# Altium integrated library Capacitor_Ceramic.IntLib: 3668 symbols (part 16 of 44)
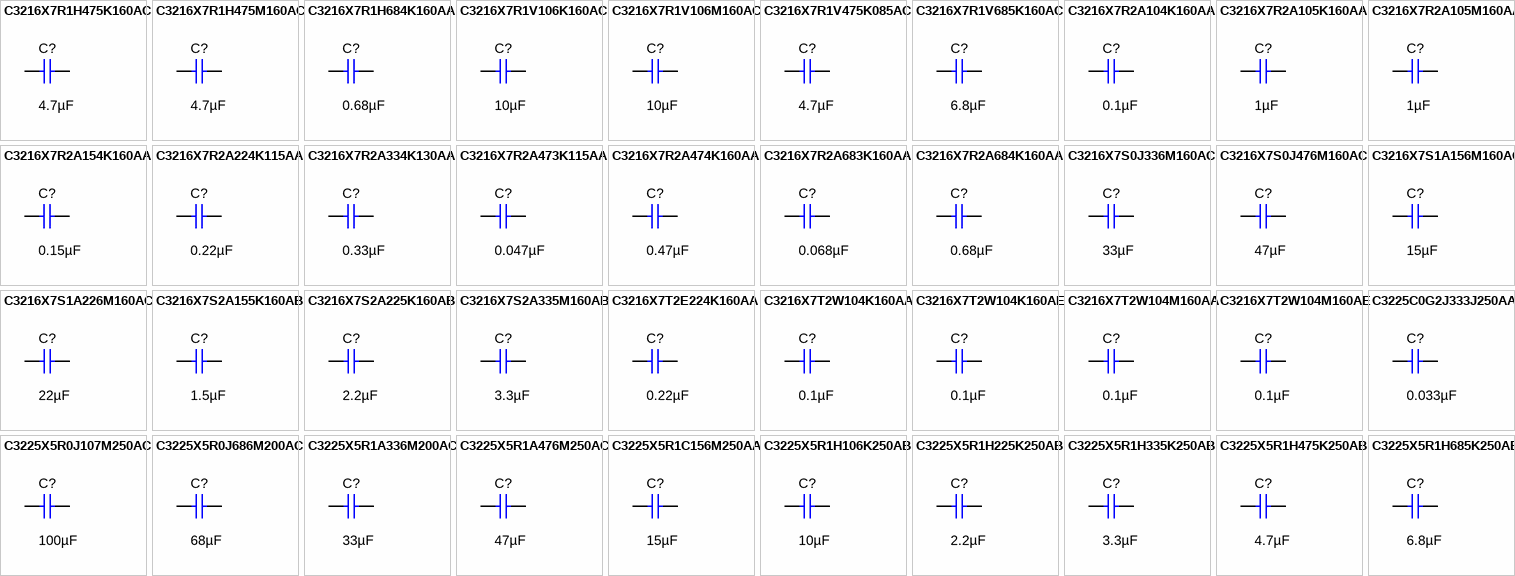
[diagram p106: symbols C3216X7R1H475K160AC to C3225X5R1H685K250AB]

## C3216X7R1H684K160AA
designator C?  ValueDisplayed: 0.68µF  (hidden comment: C3216X7R1H684K160AA)
CAP, CERM, 0.68 µF, 50 V,+/- 10%, X7R, 1206; Manufacturer: TDK; Polarized: N; CompType: Capacitor; Value: 0.68uF; U/M: EA; Cap_F: 0.00000068; Tolerance_%: 10; ESR_ohm: 0.009045; Value1: 0.009045 ohm; VDC_V: 50; Value2: 50V; IRMS_A: 2.41792; TaMin_C: -55; TaMax_C: 125; Cap_Case: 1206; SizeArea_mm2: 5.12; SizeAreaWB_mm2: 10.92; SizeX_mm: 3.2; SizeY_mm: 1.6; SizeZ_mm: 1.8; AEC Category: Q200; Green_Lifecycle: NRND; Green_REACh: Passed
signal-integrity model Cap
simulation model Cap
footprint 1206_180
footprint 1206_180M
footprint 1206_180L
pins: 1, 2

## C3216X7R1V106K160AC
designator C?  ValueDisplayed: 10µF  (hidden comment: C3216X7R1V106K160AC)
CAP, CERM, 10 µF, 35 V,+/- 10%, X7R, 1206; Manufacturer: TDK; Polarized: N; CompType: Capacitor; Value: 10uF; U/M: EA; Cap_F: 0.00001; Tolerance_%: 10; ESR_ohm: 0.002229; Value1: 0.002229 ohm; VDC_V: 35; Value2: 35V; IRMS_A: 4.85932; TaMin_C: -55; TaMax_C: 125; Cap_Case: 1206; SizeArea_mm2: 5.12; SizeAreaWB_mm2: 10.92; SizeX_mm: 3.2; SizeY_mm: 1.6; SizeZ_mm: 1.8; AEC Category: Q200
signal-integrity model Cap
simulation model Cap
footprint 1206_180
footprint 1206_180M
footprint 1206_180L
pins: 1, 2

## C3216X7R1V106M160AC
designator C?  ValueDisplayed: 10µF  (hidden comment: C3216X7R1V106M160AC)
CAP, CERM, 10 µF, 35 V,+/- 20%, X7R, 1206; Manufacturer: TDK; Polarized: N; CompType: Capacitor; Value: 10uF; U/M: EA; Cap_F: 0.00001; Tolerance_%: 20; VDC_V: 35; Value2: 35V; TaMin_C: -55; TaMax_C: 125; Cap_Case: 1206; SizeArea_mm2: 5.12; SizeAreaWB_mm2: 10.92; SizeX_mm: 3.2; SizeY_mm: 1.6; SizeZ_mm: 1.9; AEC Category: Q200; Green_Lifecycle: Active; Green_REACh: Passed
signal-integrity model Cap
simulation model Cap
footprint 1206_190
footprint 1206_190M
footprint 1206_190L
pins: 1, 2

## C3216X7R1V475K085AC
designator C?  ValueDisplayed: 4.7µF  (hidden comment: C3216X7R1V475K085AC)
CAP, CERM, 4.7 µF, 35 V,+/- 10%, X7R, 1206; Manufacturer: TDK; Polarized: N; CompType: Capacitor; Value: 4.7uF; U/M: EA; Cap_F: 0.0000047; Tolerance_%: 10; ESR_ohm: 0.003785; Value1: 0.003785 ohm; VDC_V: 35; Value2: 35V; IRMS_A: 3.73011; TaMin_C: -55; TaMax_C: 125; Cap_Case: 1206; SizeArea_mm2: 5.12; SizeAreaWB_mm2: 10.92; SizeX_mm: 3.2; SizeY_mm: 1.6; SizeZ_mm: 1.35; AEC Category: Q200
signal-integrity model Cap
simulation model Cap
footprint 1206
footprint 1206M
footprint 1206L
pins: 1, 2

## C3216X7R1V685K160AC
designator C?  ValueDisplayed: 6.8µF  (hidden comment: C3216X7R1V685K160AC)
CAP, CERM, 6.8 µF, 35 V,+/- 10%, X7R, 1206; Manufacturer: TDK; Polarized: N; CompType: Capacitor; Value: 6.8uF; U/M: EA; Cap_F: 0.0000068; Tolerance_%: 10; ESR_ohm: 0.003202; Value1: 0.003202 ohm; VDC_V: 35; Value2: 35V; IRMS_A: 4.05527; TaMin_C: -55; TaMax_C: 125; Cap_Case: 1206; SizeArea_mm2: 5.12; SizeAreaWB_mm2: 10.92; SizeX_mm: 3.2; SizeY_mm: 1.6; SizeZ_mm: 1.8; AEC Category: Q200
signal-integrity model Cap
simulation model Cap
footprint 1206_180
footprint 1206_180M
footprint 1206_180L
pins: 1, 2

## C3216X7R2A104K160AA
designator C?  ValueDisplayed: 0.1µF  (hidden comment: C3216X7R2A104K160AA)
CAP, CERM, 0.1 µF, 100 V,+/- 10%, X7R, 1206; Manufacturer: TDK; Polarized: N; CompType: Capacitor; Value: 0.1uF; U/M: EA; Cap_F: 0.0000001; Tolerance_%: 10; ESR_ohm: 0.030343; Value1: 0.030343 ohm; VDC_V: 100; Value2: 100V; IRMS_A: 1.33802; TaMin_C: -55; TaMax_C: 125; Cap_Case: 1206; SizeArea_mm2: 5.12; SizeAreaWB_mm2: 10.92; SizeX_mm: 3.2; SizeY_mm: 1.6; SizeZ_mm: 1.8; AEC Category: Q200; Green_Lifecycle: Active; Green_REACh: Passed
signal-integrity model Cap
simulation model Cap
footprint 1206_180
footprint 1206_180M
footprint 1206_180L
pins: 1, 2

## C3216X7R2A105K160AA
designator C?  ValueDisplayed: 1µF  (hidden comment: C3216X7R2A105K160AA)
CAP, CERM, 1 µF, 100 V,+/- 10%, X7R, 1206; Manufacturer: TDK; Polarized: N; CompType: Capacitor; Value: 1uF; U/M: EA; Cap_F: 0.000001; Tolerance_%: 10; ESR_ohm: 0.004575; Value1: 0.004575 ohm; VDC_V: 100; Value2: 100V; IRMS_A: 3.39639; TaMin_C: -55; TaMax_C: 125; Cap_Case: 1206; SizeArea_mm2: 5.12; SizeAreaWB_mm2: 10.92; SizeX_mm: 3.2; SizeY_mm: 1.6; SizeZ_mm: 1.8; AEC Category: Q200
signal-integrity model Cap
simulation model Cap
footprint 1206_180
footprint 1206_180M
footprint 1206_180L
pins: 1, 2

## C3216X7R2A105M160AA
designator C?  ValueDisplayed: 1µF  (hidden comment: C3216X7R2A105M160AA)
CAP, CERM, 1 µF, 100 V,+/- 20%, X7R, 1206; Manufacturer: TDK; Polarized: N; CompType: Capacitor; Value: 1uF; U/M: EA; Cap_F: 0.000001; Tolerance_%: 20; VDC_V: 100; Value2: 100V; TaMin_C: -55; TaMax_C: 125; Cap_Case: 1206; SizeArea_mm2: 5.12; SizeAreaWB_mm2: 10.92; SizeX_mm: 3.2; SizeY_mm: 1.6; SizeZ_mm: 1.35; AEC Category: Q200; Green_Lifecycle: Active; Green_REACh: Passed
signal-integrity model Cap
simulation model Cap
footprint 1206
footprint 1206M
footprint 1206L
pins: 1, 2

## C3216X7R2A154K160AA
designator C?  ValueDisplayed: 0.15µF  (hidden comment: C3216X7R2A154K160AA)
CAP, CERM, 0.15 µF, 100 V,+/- 10%, X7R, 1206; Manufacturer: TDK; Polarized: N; CompType: Capacitor; Value: 0.15uF; U/M: EA; Cap_F: 0.00000015; Tolerance_%: 10; ESR_ohm: 0.021684; Value1: 0.021684 ohm; VDC_V: 100; Value2: 100V; IRMS_A: 1.57495; TaMin_C: -55; TaMax_C: 125; Cap_Case: 1206; SizeArea_mm2: 5.12; SizeAreaWB_mm2: 10.92; SizeX_mm: 3.2; SizeY_mm: 1.6; SizeZ_mm: 1.8; AEC Category: Q200
signal-integrity model Cap
simulation model Cap
footprint 1206_180
footprint 1206_180M
footprint 1206_180L
pins: 1, 2

## C3216X7R2A224K115AA
designator C?  ValueDisplayed: 0.22µF  (hidden comment: C3216X7R2A224K115AA)
CAP, CERM, 0.22 µF, 100 V,+/- 10%, X7R, 1206; Manufacturer: TDK; Polarized: N; CompType: Capacitor; Value: 0.22uF; U/M: EA; Cap_F: 0.00000022; Tolerance_%: 10; ESR_ohm: 0.01493; Value1: 0.01493 ohm; VDC_V: 100; Value2: 100V; IRMS_A: 1.89056; TaMin_C: -55; TaMax_C: 125; Cap_Case: 1206; SizeArea_mm2: 5.12; SizeAreaWB_mm2: 10.92; SizeX_mm: 3.2; SizeY_mm: 1.6; SizeZ_mm: 1.35; AEC Category: Q200
signal-integrity model Cap
simulation model Cap
footprint 1206
footprint 1206M
footprint 1206L
pins: 1, 2

## C3216X7R2A334K130AA
designator C?  ValueDisplayed: 0.33µF  (hidden comment: C3216X7R2A334K130AA)
CAP, CERM, 0.33 µF, 100 V,+/- 10%, X7R, 1206; Manufacturer: TDK; Polarized: N; CompType: Capacitor; Value: 0.33uF; U/M: EA; Cap_F: 0.00000033; Tolerance_%: 10; ESR_ohm: 0.011504; Value1: 0.011504 ohm; VDC_V: 100; Value2: 100V; IRMS_A: 2.14919; TaMin_C: -55; TaMax_C: 125; Cap_Case: 1206; SizeArea_mm2: 5.12; SizeAreaWB_mm2: 10.92; SizeX_mm: 3.2; SizeY_mm: 1.6; SizeZ_mm: 1.5; AEC Category: Q200
signal-integrity model Cap
simulation model Cap
footprint 1206_150
footprint 1206_150M
footprint 1206_150L
pins: 1, 2

## C3216X7R2A473K115AA
designator C?  ValueDisplayed: 0.047µF  (hidden comment: C3216X7R2A473K115AA)
CAP, CERM, 0.047 µF, 100 V,+/- 10%, X7R, 1206; Manufacturer: TDK; Polarized: N; CompType: Capacitor; Value: 0.047uF; U/M: EA; Cap_F: 0.000000047; Tolerance_%: 10; ESR_ohm: 0.065629; Value1: 0.065629 ohm; VDC_V: 100; Value2: 100V; IRMS_A: 0.927421; TaMin_C: -55; TaMax_C: 125; Cap_Case: 1206; SizeArea_mm2: 5.12; SizeAreaWB_mm2: 10.92; SizeX_mm: 3.2; SizeY_mm: 1.6; SizeZ_mm: 1.35; AEC Category: Q200
signal-integrity model Cap
simulation model Cap
footprint 1206
footprint 1206M
footprint 1206L
pins: 1, 2

## C3216X7R2A474K160AA
designator C?  ValueDisplayed: 0.47µF  (hidden comment: C3216X7R2A474K160AA)
CAP, CERM, 0.47 µF, 100 V,+/- 10%, X7R, 1206; Manufacturer: TDK; Polarized: N; CompType: Capacitor; Value: 0.47uF; U/M: EA; Cap_F: 0.00000047; Tolerance_%: 10; ESR_ohm: 0.007558; Value1: 0.007558 ohm; VDC_V: 100; Value2: 100V; IRMS_A: 2.64716; TaMin_C: -55; TaMax_C: 125; Cap_Case: 1206; SizeArea_mm2: 5.12; SizeAreaWB_mm2: 10.92; SizeX_mm: 3.2; SizeY_mm: 1.6; SizeZ_mm: 1.8; AEC Category: Q200; Green_Lifecycle: Active; Green_REACh: Passed
signal-integrity model Cap
simulation model Cap
footprint 1206_180
footprint 1206_180M
footprint 1206_180L
pins: 1, 2

## C3216X7R2A683K160AA
designator C?  ValueDisplayed: 0.068µF  (hidden comment: C3216X7R2A683K160AA)
CAP, CERM, 0.068 µF, 100 V,+/- 10%, X7R, 1206; Manufacturer: TDK; Polarized: N; CompType: Capacitor; Value: 0.068uF; U/M: EA; Cap_F: 0.000000068; Tolerance_%: 10; ESR_ohm: 0.046525; Value1: 0.046525 ohm; VDC_V: 100; Value2: 100V; IRMS_A: 1.08982; TaMin_C: -55; TaMax_C: 125; Cap_Case: 1206; SizeArea_mm2: 5.12; SizeAreaWB_mm2: 10.92; SizeX_mm: 3.2; SizeY_mm: 1.6; SizeZ_mm: 1.8; AEC Category: Q200
signal-integrity model Cap
simulation model Cap
footprint 1206_180
footprint 1206_180M
footprint 1206_180L
pins: 1, 2

## C3216X7R2A684K160AA
designator C?  ValueDisplayed: 0.68µF  (hidden comment: C3216X7R2A684K160AA)
CAP, CERM, 0.68 µF, 100 V,+/- 10%, X7R, 1206; Manufacturer: TDK; Polarized: N; CompType: Capacitor; Value: 0.68uF; U/M: EA; Cap_F: 0.00000068; Tolerance_%: 10; ESR_ohm: 0.007371; Value1: 0.007371 ohm; VDC_V: 100; Value2: 100V; IRMS_A: 2.67843; TaMin_C: -55; TaMax_C: 125; Cap_Case: 1206; SizeArea_mm2: 5.12; SizeAreaWB_mm2: 10.92; SizeX_mm: 3.2; SizeY_mm: 1.6; SizeZ_mm: 1.8; AEC Category: Q200
signal-integrity model Cap
simulation model Cap
footprint 1206_180
footprint 1206_180M
footprint 1206_180L
pins: 1, 2

## C3216X7S0J336M160AC
designator C?  ValueDisplayed: 33µF  (hidden comment: C3216X7S0J336M160AC)
CAP, CERM, 33 µF, 6.3 V,+/- 20%, X7S, 1206; Manufacturer: TDK; Polarized: N; CompType: Capacitor; Value: 33uF; U/M: EA; Cap_F: 0.000033; Tolerance_%: 20; ESR_ohm: 0.002648; Value1: 0.002648 ohm; VDC_V: 6.3; Value2: 6.3V; IRMS_A: 4.45864; TaMin_C: -55; TaMax_C: 125; Cap_Case: 1206; SizeArea_mm2: 5.12; SizeAreaWB_mm2: 10.92; SizeX_mm: 3.2; SizeY_mm: 1.6; SizeZ_mm: 1.8; AEC Category: Q200
signal-integrity model Cap
simulation model Cap
footprint 1206_180
footprint 1206_180M
footprint 1206_180L
pins: 1, 2

## C3216X7S0J476M160AC
designator C?  ValueDisplayed: 47µF  (hidden comment: C3216X7S0J476M160AC)
CAP, CERM, 47 µF, 6.3 V,+/- 20%, X7S, 1206; Manufacturer: TDK; Polarized: N; CompType: Capacitor; Value: 47uF; U/M: EA; Cap_F: 0.000047; Tolerance_%: 20; ESR_ohm: 0.002082; Value1: 0.002082 ohm; VDC_V: 6.3; Value2: 6.3V; IRMS_A: 5.02786; TaMin_C: -55; TaMax_C: 125; Cap_Case: 1206; SizeArea_mm2: 5.12; SizeAreaWB_mm2: 10.92; SizeX_mm: 3.2; SizeY_mm: 1.6; SizeZ_mm: 1.8; AEC Category: Q200
signal-integrity model Cap
simulation model Cap
footprint 1206_180
footprint 1206_180M
footprint 1206_180L
pins: 1, 2

## C3216X7S1A156M160AC
designator C?  ValueDisplayed: 15µF  (hidden comment: C3216X7S1A156M160AC)
CAP, CERM, 15 µF, 10 V,+/- 20%, X7S, 1206; Manufacturer: TDK; Polarized: N; CompType: Capacitor; Value: 15uF; U/M: EA; Cap_F: 0.000015; Tolerance_%: 20; ESR_ohm: 0.002667; Value1: 0.002667 ohm; VDC_V: 10; Value2: 10V; IRMS_A: 4.44289; TaMin_C: -55; TaMax_C: 125; Cap_Case: 1206; SizeArea_mm2: 5.12; SizeAreaWB_mm2: 10.92; SizeX_mm: 3.2; SizeY_mm: 1.6; SizeZ_mm: 1.8; AEC Category: Q200
signal-integrity model Cap
simulation model Cap
footprint 1206_180
footprint 1206_180M
footprint 1206_180L
pins: 1, 2

## C3216X7S1A226M160AC
designator C?  ValueDisplayed: 22µF  (hidden comment: C3216X7S1A226M160AC)
CAP, CERM, 22 µF, 10 V,+/- 20%, X7S, 1206; Manufacturer: TDK; Polarized: N; CompType: Capacitor; Value: 22uF; U/M: EA; Cap_F: 0.000022; Tolerance_%: 20; ESR_ohm: 0.002398; Value1: 0.002398 ohm; VDC_V: 10; Value2: 10V; IRMS_A: 4.68507; TaMin_C: -55; TaMax_C: 125; Cap_Case: 1206; SizeArea_mm2: 5.12; SizeAreaWB_mm2: 10.92; SizeX_mm: 3.2; SizeY_mm: 1.6; SizeZ_mm: 1.8; AEC Category: Q200
signal-integrity model Cap
simulation model Cap
footprint 1206_180
footprint 1206_180M
footprint 1206_180L
pins: 1, 2

## C3216X7S2A155K160AB
designator C?  ValueDisplayed: 1.5µF  (hidden comment: C3216X7S2A155K160AB)
CAP, CERM, 1.5 µF, 100 V,+/- 10%, X7S, 1206; Manufacturer: TDK; Polarized: N; CompType: Capacitor; Value: 1.5uF; U/M: EA; Cap_F: 0.0000015; Tolerance_%: 10; ESR_ohm: 0.006319; Value1: 0.006319 ohm; VDC_V: 100; Value2: 100V; IRMS_A: 2.88897; TaMin_C: -55; TaMax_C: 125; Cap_Case: 1206; SizeArea_mm2: 5.12; SizeAreaWB_mm2: 10.92; SizeX_mm: 3.2; SizeY_mm: 1.6; SizeZ_mm: 1.8; AEC Category: Q200
signal-integrity model Cap
simulation model Cap
footprint 1206_180
footprint 1206_180M
footprint 1206_180L
pins: 1, 2

## C3216X7S2A225K160AB
designator C?  ValueDisplayed: 2.2µF  (hidden comment: C3216X7S2A225K160AB)
CAP, CERM, 2.2 µF, 100 V,+/- 10%, X7S, 1206; Manufacturer: TDK; Polarized: N; CompType: Capacitor; Value: 2.2uF; U/M: EA; Cap_F: 0.0000022; Tolerance_%: 10; ESR_ohm: 0.005718; Value1: 0.005718 ohm; VDC_V: 100; Value2: 100V; IRMS_A: 3.03632; TaMin_C: -55; TaMax_C: 125; Cap_Case: 1206; SizeArea_mm2: 5.12; SizeAreaWB_mm2: 10.92; SizeX_mm: 3.2; SizeY_mm: 1.6; SizeZ_mm: 1.8; AEC Category: Q200
signal-integrity model Cap
simulation model Cap
footprint 1206_180
footprint 1206_180M
footprint 1206_180L
pins: 1, 2

## C3216X7S2A335M160AB
designator C?  ValueDisplayed: 3.3µF  (hidden comment: C3216X7S2A335M160AB)
CAP, CERM, 3.3 µF, 100 V,+/- 20%, X7S, 1206; Manufacturer: TDK; Polarized: N; CompType: Capacitor; Value: 3.3uF; U/M: EA; Cap_F: 0.0000033; Tolerance_%: 20; ESR_ohm: 0.003048; Value1: 0.003048 ohm; VDC_V: 100; Value2: 100V; IRMS_A: 4.15703; TaMin_C: -55; TaMax_C: 125; Cap_Case: 1206; SizeArea_mm2: 5.12; SizeAreaWB_mm2: 10.92; SizeX_mm: 3.2; SizeY_mm: 1.6; SizeZ_mm: 1.9; AEC Category: Q200
signal-integrity model Cap
simulation model Cap
footprint 1206_190
footprint 1206_190M
footprint 1206_190L
pins: 1, 2

## C3216X7T2E224K160AA
designator C?  ValueDisplayed: 0.22µF  (hidden comment: C3216X7T2E224K160AA)
CAP, CERM, 0.22 µF, 250 V,+/- 10%, X7T, 1206; Manufacturer: TDK; Polarized: N; CompType: Capacitor; Value: 0.22uF; U/M: EA; Cap_F: 0.00000022; Tolerance_%: 10; VDC_V: 250; Value2: 250V; TaMin_C: -55; TaMax_C: 125; Cap_Case: 1206; SizeArea_mm2: 5.12; SizeAreaWB_mm2: 10.92; SizeX_mm: 3.2; SizeY_mm: 1.6; SizeZ_mm: 1.9; AEC Category: Q200; Green_Lifecycle: Active; Green_REACh: Passed
signal-integrity model Cap
simulation model Cap
footprint 1206_190
footprint 1206_190M
footprint 1206_190L
pins: 1, 2

## C3216X7T2W104K160AA
designator C?  ValueDisplayed: 0.1µF  (hidden comment: C3216X7T2W104K160AA)
CAP, CERM, 0.1 µF, 450 V,+/- 10%, X7T, 1206; Manufacturer: TDK; Polarized: N; CompType: Capacitor; Value: 0.1uF; U/M: EA; Cap_F: 0.0000001; Tolerance_%: 10; VDC_V: 450; Value2: 450V; TaMin_C: -55; TaMax_C: 125; Cap_Case: 1206; SizeArea_mm2: 5.12; SizeAreaWB_mm2: 10.92; SizeX_mm: 3.2; SizeY_mm: 1.6; SizeZ_mm: 1.9; AEC Category: Q200; Green_Lifecycle: Not Set; Green_REACh: Incomplete
signal-integrity model Cap
simulation model Cap
footprint 1206_190
footprint 1206_190M
footprint 1206_190L
pins: 1, 2

## C3216X7T2W104K160AE
designator C?  ValueDisplayed: 0.1µF  (hidden comment: C3216X7T2W104K160AE)
CAP, CERM, 0.1 µF, 450 V,+/- 10%, X7T, 1206; Manufacturer: TDK; Polarized: N; CompType: Capacitor; Value: 0.1uF; U/M: EA; Cap_F: 0.0000001; Tolerance_%: 10; VDC_V: 450; Value2: 450V; TaMin_C: -55; TaMax_C: 125; Cap_Case: 1206; SizeArea_mm2: 5.12; SizeAreaWB_mm2: 10.92; SizeX_mm: 3.2; SizeY_mm: 1.6; SizeZ_mm: 1.8; AEC Category: Q200; Green_Lifecycle: Not Set; Green_REACh: Incomplete
signal-integrity model Cap
simulation model Cap
footprint 1206_180
footprint 1206_180M
footprint 1206_180L
pins: 1, 2

## C3216X7T2W104M160AA
designator C?  ValueDisplayed: 0.1µF  (hidden comment: C3216X7T2W104M160AA)
CAP, CERM, 0.1 µF, 450 V,+/- 20%, X7T, 1206; Manufacturer: TDK; Polarized: N; CompType: Capacitor; Value: 0.1uF; U/M: EA; Cap_F: 0.0000001; Tolerance_%: 20; VDC_V: 450; Value2: 450V; TaMin_C: -55; TaMax_C: 125; Cap_Case: 1206; SizeArea_mm2: 5.12; SizeAreaWB_mm2: 10.92; SizeX_mm: 3.2; SizeY_mm: 1.6; SizeZ_mm: 1.8; AEC Category: Q200; Green_Lifecycle: Not Set; Green_REACh: Incomplete
signal-integrity model Cap
simulation model Cap
footprint 1206_180
footprint 1206_180M
footprint 1206_180L
pins: 1, 2

## C3216X7T2W104M160AE
designator C?  ValueDisplayed: 0.1µF  (hidden comment: C3216X7T2W104M160AE)
CAP, CERM, 0.1 µF, 450 V,+/- 20%, X7T, 1206; Manufacturer: TDK; Polarized: N; CompType: Capacitor; Value: 0.1uF; U/M: EA; Cap_F: 0.0000001; Tolerance_%: 20; VDC_V: 450; Value2: 450V; TaMin_C: -55; TaMax_C: 125; Cap_Case: 1206; SizeArea_mm2: 5.12; SizeAreaWB_mm2: 10.92; SizeX_mm: 3.2; SizeY_mm: 1.6; SizeZ_mm: 1.8; AEC Category: Q200; Green_Lifecycle: Not Set; Green_REACh: Incomplete
signal-integrity model Cap
simulation model Cap
footprint 1206_180
footprint 1206_180M
footprint 1206_180L
pins: 1, 2

## C3225C0G2J333J250AA
designator C?  ValueDisplayed: 0.033µF  (hidden comment: C3225C0G2J333J250AA)
CAP, CERM, 0.033 µF, 630 V,+/- 5%, C0G/NP0, 1210; Manufacturer: TDK; Polarized: N; CompType: Capacitor; Value: 0.033uF; U/M: EA; Cap_F: 0.000000033; Tolerance_%: 5; VDC_V: 630; Value2: 630V; TaMin_C: -55; TaMax_C: 125; Cap_Case: 1210; SizeArea_mm2: 8; SizeAreaWB_mm2: 14.7; SizeX_mm: 3.2; SizeY_mm: 2.5; SizeZ_mm: 2.8; AEC Category: Q200
signal-integrity model Cap
simulation model Cap
footprint 1210_280
pins: 1, 2

## C3225X5R0J107M250AC
designator C?  ValueDisplayed: 100µF  (hidden comment: C3225X5R0J107M250AC)
CAP, CERM, 100 µF, 6.3 V,+/- 20%, X5R, 1210; Manufacturer: TDK; Polarized: N; CompType: Capacitor; Value: 100uF; U/M: EA; Cap_F: 0.0001; Tolerance_%: 20; ESR_ohm: 0.005496; Value1: 0.005496 ohm; VDC_V: 6.3; Value2: 6.3V; IRMS_A: 3.13651; TaMin_C: -55; TaMax_C: 85; Cap_Case: 1210; SizeArea_mm2: 8; SizeAreaWB_mm2: 14.7; SizeX_mm: 3.2; SizeY_mm: 2.5; SizeZ_mm: 2.8; AEC Category: Q200; Green_Lifecycle: Active; Green_REACh: Passed
signal-integrity model Cap
simulation model Cap
footprint 1210_280
pins: 1, 2

## C3225X5R0J686M200AC
designator C?  ValueDisplayed: 68µF  (hidden comment: C3225X5R0J686M200AC)
CAP, CERM, 68 µF, 6.3 V,+/- 20%, X5R, 1210; Manufacturer: TDK; Polarized: N; CompType: Capacitor; Value: 68uF; U/M: EA; Cap_F: 0.000068; Tolerance_%: 20; ESR_ohm: 0.001888; Value1: 0.001888 ohm; VDC_V: 6.3; Value2: 6.3V; IRMS_A: 5.35045; TaMin_C: -55; TaMax_C: 85; Cap_Case: 1210; SizeArea_mm2: 8; SizeAreaWB_mm2: 14.7; SizeX_mm: 3.2; SizeY_mm: 2.5; SizeZ_mm: 2.2; AEC Category: Q200
signal-integrity model Cap
simulation model Cap
footprint 1210_220
footprint 1210_220M
footprint 1210_220L
pins: 1, 2

## C3225X5R1A336M200AC
designator C?  ValueDisplayed: 33µF  (hidden comment: C3225X5R1A336M200AC)
CAP, CERM, 33 µF, 10 V,+/- 20%, X5R, 1210; Manufacturer: TDK; Polarized: N; CompType: Capacitor; Value: 33uF; U/M: EA; Cap_F: 0.000033; Tolerance_%: 20; ESR_ohm: 0.00252; Value1: 0.00252 ohm; VDC_V: 10; Value2: 10V; IRMS_A: 4.63172; TaMin_C: -55; TaMax_C: 85; Cap_Case: 1210; SizeArea_mm2: 8; SizeAreaWB_mm2: 14.7; SizeX_mm: 3.2; SizeY_mm: 2.5; SizeZ_mm: 2.2; AEC Category: Q200
signal-integrity model Cap
simulation model Cap
footprint 1210_220
footprint 1210_220M
footprint 1210_220L
pins: 1, 2

## C3225X5R1A476M250AC
designator C?  ValueDisplayed: 47µF  (hidden comment: C3225X5R1A476M250AC)
CAP, CERM, 47 µF, 10 V,+/- 20%, X5R, 1210; Manufacturer: TDK; Polarized: N; CompType: Capacitor; Value: 47uF; U/M: EA; Cap_F: 0.000047; Tolerance_%: 20; ESR_ohm: 0.003602; Value1: 0.003602 ohm; VDC_V: 10; Value2: 10V; IRMS_A: 3.87414; TaMin_C: -55; TaMax_C: 85; Cap_Case: 1210; SizeArea_mm2: 8; SizeAreaWB_mm2: 14.7; SizeX_mm: 3.2; SizeY_mm: 2.5; SizeZ_mm: 2.8; AEC Category: Q200; Green_Lifecycle: Active; Green_REACh: Passed
signal-integrity model Cap
simulation model Cap
footprint 1210_280
pins: 1, 2

## C3225X5R1C156M250AA
designator C?  ValueDisplayed: 15µF  (hidden comment: C3225X5R1C156M250AA)
CAP, CERM, 15 µF, 16 V,+/- 20%, X5R, 1210; Manufacturer: TDK; Polarized: N; CompType: Capacitor; Value: 15uF; U/M: EA; Cap_F: 0.000015; Tolerance_%: 20; ESR_ohm: 0.002949; Value1: 0.002949 ohm; VDC_V: 16; Value2: 16V; IRMS_A: 4.28133; TaMin_C: -55; TaMax_C: 85; Cap_Case: 1210; SizeArea_mm2: 8; SizeAreaWB_mm2: 14.7; SizeX_mm: 3.2; SizeY_mm: 2.5; SizeZ_mm: 2.8; AEC Category: Q200
signal-integrity model Cap
simulation model Cap
footprint 1210_280
pins: 1, 2

## C3225X5R1H106K250AB
designator C?  ValueDisplayed: 10µF  (hidden comment: C3225X5R1H106K250AB)
CAP, CERM, 10 µF, 50 V,+/- 10%, X5R, 1210; Manufacturer: TDK; Polarized: N; CompType: Capacitor; Value: 10uF; U/M: EA; Cap_F: 0.00001; Tolerance_%: 10; VDC_V: 50; Value2: 50V; TaMin_C: -55; TaMax_C: 85; Cap_Case: 1210; SizeArea_mm2: 8; SizeAreaWB_mm2: 14.7; SizeX_mm: 3.2; SizeY_mm: 2.5; SizeZ_mm: 2.8; AEC Category: Q200; Green_Lifecycle: Active; Green_REACh: Passed
signal-integrity model Cap
simulation model Cap
footprint 1210_280
pins: 1, 2

## C3225X5R1H225K250AB
designator C?  ValueDisplayed: 2.2µF  (hidden comment: C3225X5R1H225K250AB)
CAP, CERM, 2.2 µF, 50 V,+/- 10%, X5R, 1210; Manufacturer: TDK; Polarized: N; CompType: Capacitor; Value: 2.2uF; U/M: EA; Cap_F: 0.0000022; Tolerance_%: 10; ESR_ohm: 0.00536; Value1: 0.00536 ohm; VDC_V: 50; Value2: 50V; IRMS_A: 3.17778; TaMin_C: -55; TaMax_C: 85; Cap_Case: 1210; SizeArea_mm2: 8; SizeAreaWB_mm2: 14.7; SizeX_mm: 3.2; SizeY_mm: 2.5; SizeZ_mm: 2.8; AEC Category: Q200
signal-integrity model Cap
simulation model Cap
footprint 1210_280
pins: 1, 2

## C3225X5R1H335K250AB
designator C?  ValueDisplayed: 3.3µF  (hidden comment: C3225X5R1H335K250AB)
CAP, CERM, 3.3 µF, 50 V,+/- 10%, X5R, 1210; Manufacturer: TDK; Polarized: N; CompType: Capacitor; Value: 3.3uF; U/M: EA; Cap_F: 0.0000033; Tolerance_%: 10; ESR_ohm: 0.003158; Value1: 0.003158 ohm; VDC_V: 50; Value2: 50V; IRMS_A: 4.13891; TaMin_C: -55; TaMax_C: 85; Cap_Case: 1210; SizeArea_mm2: 8; SizeAreaWB_mm2: 14.7; SizeX_mm: 3.2; SizeY_mm: 2.5; SizeZ_mm: 2.8; AEC Category: Q200
signal-integrity model Cap
simulation model Cap
footprint 1210_280
pins: 1, 2

## C3225X5R1H475K250AB
designator C?  ValueDisplayed: 4.7µF  (hidden comment: C3225X5R1H475K250AB)
CAP, CERM, 4.7 µF, 50 V,+/- 10%, X5R, 1210; Manufacturer: TDK; Polarized: N; CompType: Capacitor; Value: 4.7uF; U/M: EA; Cap_F: 0.0000047; Tolerance_%: 10; ESR_ohm: 0.003166; Value1: 0.003166 ohm; VDC_V: 50; Value2: 50V; IRMS_A: 4.13311; TaMin_C: -55; TaMax_C: 85; Cap_Case: 1210; SizeArea_mm2: 8; SizeAreaWB_mm2: 14.7; SizeX_mm: 3.2; SizeY_mm: 2.5; SizeZ_mm: 2.8; AEC Category: Q200; Green_Lifecycle: NRND; Green_REACh: Passed
signal-integrity model Cap
simulation model Cap
footprint 1210_280
pins: 1, 2

## C3225X5R1H685K250AB
designator C?  ValueDisplayed: 6.8µF  (hidden comment: C3225X5R1H685K250AB)
CAP, CERM, 6.8 µF, 50 V,+/- 10%, X5R, 1210; Manufacturer: TDK; Polarized: N; CompType: Capacitor; Value: 6.8uF; U/M: EA; Cap_F: 0.0000068; Tolerance_%: 10; ESR_ohm: 0.002622; Value1: 0.002622 ohm; VDC_V: 50; Value2: 50V; IRMS_A: 4.5415; TaMin_C: -55; TaMax_C: 85; Cap_Case: 1210; SizeArea_mm2: 8; SizeAreaWB_mm2: 14.7; SizeX_mm: 3.2; SizeY_mm: 2.5; SizeZ_mm: 2.8; AEC Category: Q200
signal-integrity model Cap
simulation model Cap
footprint 1210_280
pins: 1, 2

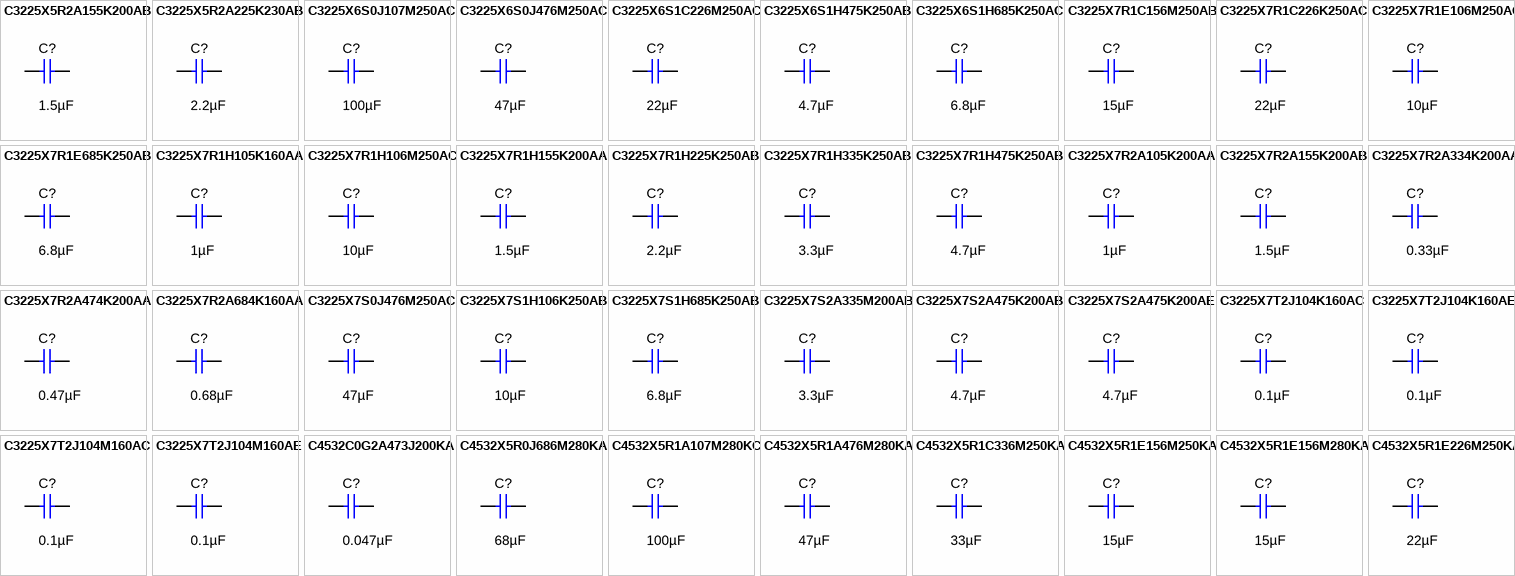
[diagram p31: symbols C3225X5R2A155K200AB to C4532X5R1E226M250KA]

## C3225X5R2A155K200AB
designator C?  ValueDisplayed: 1.5µF  (hidden comment: C3225X5R2A155K200AB)
CAP, CERM, 1.5 µF, 100 V,+/- 10%, X5R, 1210; Manufacturer: TDK; Polarized: N; CompType: Capacitor; Value: 1.5uF; U/M: EA; Cap_F: 0.0000015; Tolerance_%: 10; ESR_ohm: 0.003867; Value1: 0.003867 ohm; VDC_V: 100; Value2: 100V; IRMS_A: 3.74252; TaMin_C: -55; TaMax_C: 85; Cap_Case: 1210; SizeArea_mm2: 8; SizeAreaWB_mm2: 14.7; SizeX_mm: 3.2; SizeY_mm: 2.5; SizeZ_mm: 2.2; AEC Category: Q200
signal-integrity model Cap
simulation model Cap
footprint 1210_220
footprint 1210_220M
footprint 1210_220L
pins: 1, 2

## C3225X5R2A225K230AB
designator C?  ValueDisplayed: 2.2µF  (hidden comment: C3225X5R2A225K230AB)
CAP, CERM, 2.2 µF, 100 V,+/- 10%, X5R, 1210; Manufacturer: TDK; Polarized: N; CompType: Capacitor; Value: 2.2uF; U/M: EA; Cap_F: 0.0000022; Tolerance_%: 10; ESR_ohm: 0.00173; Value1: 0.00173 ohm; VDC_V: 100; Value2: 100V; IRMS_A: 5.59317; TaMin_C: -55; TaMax_C: 85; Cap_Case: 1210; SizeArea_mm2: 8; SizeAreaWB_mm2: 14.7; SizeX_mm: 3.2; SizeY_mm: 2.5; AEC Category: Q200; Green_Lifecycle: NRND; Green_REACh: Passed
signal-integrity model Cap
simulation model Cap
footprint 1210_250
footprint 1210_250M
footprint 1210_250L
pins: 1, 2

## C3225X6S0J107M250AC
designator C?  ValueDisplayed: 100µF  (hidden comment: C3225X6S0J107M250AC)
CAP, CERM, 100 µF, 6.3 V,+/- 20%, X6S, 1210; Manufacturer: TDK; Polarized: N; CompType: Capacitor; Value: 100uF; U/M: EA; Cap_F: 0.0001; Tolerance_%: 20; ESR_ohm: 0.005496; Value1: 0.005496 ohm; VDC_V: 6.3; Value2: 6.3V; IRMS_A: 3.13651; TaMin_C: -55; TaMax_C: 105; Cap_Case: 1210; SizeArea_mm2: 8; SizeAreaWB_mm2: 14.7; SizeX_mm: 3.2; SizeY_mm: 2.5; SizeZ_mm: 2.8; AEC Category: Q200
signal-integrity model Cap
simulation model Cap
footprint 1210_280
pins: 1, 2

## C3225X6S0J476M250AC
designator C?  ValueDisplayed: 47µF  (hidden comment: C3225X6S0J476M250AC)
CAP, CERM, 47 µF, 6.3 V,+/- 20%, X6S, 1210; Manufacturer: TDK; Polarized: N; CompType: Capacitor; Value: 47uF; U/M: EA; Cap_F: 0.000047; Tolerance_%: 20; ESR_ohm: 0.003602; Value1: 0.003602 ohm; VDC_V: 6.3; Value2: 6.3V; IRMS_A: 3.87414; TaMin_C: -55; TaMax_C: 105; Cap_Case: 1210; SizeArea_mm2: 8; SizeAreaWB_mm2: 14.7; SizeX_mm: 3.2; SizeY_mm: 2.5; SizeZ_mm: 2.8; AEC Category: Q200
signal-integrity model Cap
simulation model Cap
footprint 1210_280
pins: 1, 2

## C3225X6S1C226M250AC
designator C?  ValueDisplayed: 22µF  (hidden comment: C3225X6S1C226M250AC)
CAP, CERM, 22 µF, 16 V,+/- 20%, X6S, 1210; Manufacturer: TDK; Polarized: N; CompType: Capacitor; Value: 22uF; U/M: EA; Cap_F: 0.000022; Tolerance_%: 20; ESR_ohm: 0.002582; Value1: 0.002582 ohm; VDC_V: 16; Value2: 16V; IRMS_A: 4.57562; TaMin_C: -55; TaMax_C: 105; Cap_Case: 1210; SizeArea_mm2: 8; SizeAreaWB_mm2: 14.7; SizeX_mm: 3.2; SizeY_mm: 2.5; SizeZ_mm: 2.8; AEC Category: Q200
signal-integrity model Cap
simulation model Cap
footprint 1210_280
pins: 1, 2

## C3225X6S1H475K250AB
designator C?  ValueDisplayed: 4.7µF  (hidden comment: C3225X6S1H475K250AB)
CAP, CERM, 4.7 µF, 50 V,+/- 10%, X6S, 1210; Manufacturer: TDK; Polarized: N; CompType: Capacitor; Value: 4.7uF; U/M: EA; Cap_F: 0.0000047; Tolerance_%: 10; ESR_ohm: 0.003166; Value1: 0.003166 ohm; VDC_V: 50; Value2: 50V; IRMS_A: 4.13311; TaMin_C: -55; TaMax_C: 105; Cap_Case: 1210; SizeArea_mm2: 8; SizeAreaWB_mm2: 14.7; SizeX_mm: 3.2; SizeY_mm: 2.5; SizeZ_mm: 2.8; AEC Category: Q200
signal-integrity model Cap
simulation model Cap
footprint 1210_280
pins: 1, 2

## C3225X6S1H685K250AC
designator C?  ValueDisplayed: 6.8µF  (hidden comment: C3225X6S1H685K250AC)
CAP, CERM, 6.8 µF, 50 V,+/- 10%, X6S, 1210; Manufacturer: TDK; Polarized: N; CompType: Capacitor; Value: 6.8uF; U/M: EA; Cap_F: 0.0000068; Tolerance_%: 10; ESR_ohm: 0.002622; Value1: 0.002622 ohm; VDC_V: 50; Value2: 50V; IRMS_A: 4.5415; TaMin_C: -55; TaMax_C: 105; Cap_Case: 1210; SizeArea_mm2: 8; SizeAreaWB_mm2: 14.7; SizeX_mm: 3.2; SizeY_mm: 2.5; SizeZ_mm: 2.8; AEC Category: Q200
signal-integrity model Cap
simulation model Cap
footprint 1210_280
pins: 1, 2

## C3225X7R1C156M250AB
designator C?  ValueDisplayed: 15µF  (hidden comment: C3225X7R1C156M250AB)
CAP, CERM, 15 µF, 16 V,+/- 20%, X7R, 1210; Manufacturer: TDK; Polarized: N; CompType: Capacitor; Value: 15uF; U/M: EA; Cap_F: 0.000015; Tolerance_%: 20; ESR_ohm: 0.002949; Value1: 0.002949 ohm; VDC_V: 16; Value2: 16V; IRMS_A: 4.28133; TaMin_C: -55; TaMax_C: 125; Cap_Case: 1210; SizeArea_mm2: 8; SizeAreaWB_mm2: 14.7; SizeX_mm: 3.2; SizeY_mm: 2.5; SizeZ_mm: 2.8; AEC Category: Q200
signal-integrity model Cap
simulation model Cap
footprint 1210_280
pins: 1, 2

## C3225X7R1C226K250AC
designator C?  ValueDisplayed: 22µF  (hidden comment: C3225X7R1C226K250AC)
CAP, CERM, 22 µF, 16 V,+/- 10%, X7R, 1210; Manufacturer: TDK; Polarized: N; CompType: Capacitor; Value: 22uF; U/M: EA; Cap_F: 0.000022; Tolerance_%: 10; ESR_ohm: 0.002582; Value1: 0.002582 ohm; VDC_V: 16; Value2: 16V; IRMS_A: 4.57562; TaMin_C: -55; TaMax_C: 125; Cap_Case: 1210; SizeArea_mm2: 8; SizeAreaWB_mm2: 14.7; SizeX_mm: 3.2; SizeY_mm: 2.5; SizeZ_mm: 2.8; AEC Category: Q200; Green_Lifecycle: Active; Green_REACh: Passed
signal-integrity model Cap
simulation model Cap
footprint 1210_280
pins: 1, 2

## C3225X7R1E106M250AC
designator C?  ValueDisplayed: 10µF  (hidden comment: C3225X7R1E106M250AC)
CAP, CERM, 10 µF, 25 V,+/- 20%, X7R, 1210; Manufacturer: TDK; Polarized: N; CompType: Capacitor; Value: 10uF; U/M: EA; Cap_F: 0.00001; Tolerance_%: 20; VDC_V: 25; Value2: 25V; TaMin_C: -55; TaMax_C: 125; Cap_Case: 1210; SizeArea_mm2: 8; SizeAreaWB_mm2: 14.7; SizeX_mm: 3.2; SizeY_mm: 2.5; SizeZ_mm: 2.8; AEC Category: Q200; Green_Lifecycle: Active; Green_REACh: Passed
signal-integrity model Cap
simulation model Cap
footprint 1210_280
pins: 1, 2

## C3225X7R1E685K250AB
designator C?  ValueDisplayed: 6.8µF  (hidden comment: C3225X7R1E685K250AB)
CAP, CERM, 6.8 µF, 25 V,+/- 10%, X7R, 1210; Manufacturer: TDK; Polarized: N; CompType: Capacitor; Value: 6.8uF; U/M: EA; Cap_F: 0.0000068; Tolerance_%: 10; ESR_ohm: 0.004043; Value1: 0.004043 ohm; VDC_V: 25; Value2: 25V; IRMS_A: 3.65691; TaMin_C: -55; TaMax_C: 125; Cap_Case: 1210; SizeArea_mm2: 8; SizeAreaWB_mm2: 14.7; SizeX_mm: 3.2; SizeY_mm: 2.5; SizeZ_mm: 2.8; AEC Category: Q200
signal-integrity model Cap
simulation model Cap
footprint 1210_280
pins: 1, 2

## C3225X7R1H105K160AA
designator C?  ValueDisplayed: 1µF  (hidden comment: C3225X7R1H105K160AA)
CAP, CERM, 1 µF, 50 V,+/- 10%, X7R, 1210; Manufacturer: TDK; Polarized: N; CompType: Capacitor; Value: 1uF; U/M: EA; Cap_F: 0.000001; Tolerance_%: 10; ESR_ohm: 0.007168; Value1: 0.007168 ohm; VDC_V: 50; Value2: 50V; IRMS_A: 2.75026; TaMin_C: -55; TaMax_C: 125; Cap_Case: 1210; SizeArea_mm2: 8; SizeAreaWB_mm2: 14.7; SizeX_mm: 3.2; SizeY_mm: 2.5; SizeZ_mm: 1.8; AEC Category: Q200
signal-integrity model Cap
simulation model Cap
footprint 1210_180
footprint 1210_180M
footprint 1210_180L
pins: 1, 2

## C3225X7R1H106M250AC
designator C?  ValueDisplayed: 10µF  (hidden comment: C3225X7R1H106M250AC)
CAP, CERM, 10 µF, 50 V,+/- 20%, X7R, 1210; Manufacturer: TDK; Polarized: N; CompType: Capacitor; Value: 10uF; U/M: EA; Cap_F: 0.00001; Tolerance_%: 20; VDC_V: 50; Value2: 50V; TaMin_C: -55; TaMax_C: 125; Cap_Case: 1210; SizeArea_mm2: 8; SizeAreaWB_mm2: 14.7; SizeX_mm: 3.2; SizeY_mm: 2.5; SizeZ_mm: 2.8; AEC Category: Q200; Green_Lifecycle: Active; Green_REACh: Passed
signal-integrity model Cap
simulation model Cap
footprint 1210_280
pins: 1, 2

## C3225X7R1H155K200AA
designator C?  ValueDisplayed: 1.5µF  (hidden comment: C3225X7R1H155K200AA)
CAP, CERM, 1.5 µF, 50 V,+/- 10%, X7R, 1210; Manufacturer: TDK; Polarized: N; CompType: Capacitor; Value: 1.5uF; U/M: EA; Cap_F: 0.0000015; Tolerance_%: 10; ESR_ohm: 0.003947; Value1: 0.003947 ohm; VDC_V: 50; Value2: 50V; IRMS_A: 3.70421; TaMin_C: -55; TaMax_C: 125; Cap_Case: 1210; SizeArea_mm2: 8; SizeAreaWB_mm2: 14.7; SizeX_mm: 3.2; SizeY_mm: 2.5; SizeZ_mm: 2.2; AEC Category: Q200
signal-integrity model Cap
simulation model Cap
footprint 1210_220
footprint 1210_220M
footprint 1210_220L
pins: 1, 2

## C3225X7R1H225K250AB
designator C?  ValueDisplayed: 2.2µF  (hidden comment: C3225X7R1H225K250AB)
CAP, CERM, 2.2 µF, 50 V,+/- 10%, X7R, 1210; Manufacturer: TDK; Polarized: N; CompType: Capacitor; Value: 2.2uF; U/M: EA; Cap_F: 0.0000022; Tolerance_%: 10; ESR_ohm: 0.00536; Value1: 0.00536 ohm; VDC_V: 50; Value2: 50V; IRMS_A: 3.17778; TaMin_C: -55; TaMax_C: 125; Cap_Case: 1210; SizeArea_mm2: 8; SizeAreaWB_mm2: 14.7; SizeX_mm: 3.2; SizeY_mm: 2.5; SizeZ_mm: 2.8; AEC Category: Q200; Green_Lifecycle: Active; Green_REACh: Passed
signal-integrity model Cap
simulation model Cap
footprint 1210_280
pins: 1, 2

## C3225X7R1H335K250AB
designator C?  ValueDisplayed: 3.3µF  (hidden comment: C3225X7R1H335K250AB)
CAP, CERM, 3.3 µF, 50 V,+/- 10%, X7R, 1210; Manufacturer: TDK; Polarized: N; CompType: Capacitor; Value: 3.3uF; U/M: EA; Cap_F: 0.0000033; Tolerance_%: 10; ESR_ohm: 0.003158; Value1: 0.003158 ohm; VDC_V: 50; Value2: 50V; IRMS_A: 4.13891; TaMin_C: -55; TaMax_C: 125; Cap_Case: 1210; SizeArea_mm2: 8; SizeAreaWB_mm2: 14.7; SizeX_mm: 3.2; SizeY_mm: 2.5; SizeZ_mm: 2.8; AEC Category: Q200; Green_Lifecycle: NRND; Green_REACh: Passed
signal-integrity model Cap
simulation model Cap
footprint 1210_280
pins: 1, 2

## C3225X7R1H475K250AB
designator C?  ValueDisplayed: 4.7µF  (hidden comment: C3225X7R1H475K250AB)
CAP, CERM, 4.7 µF, 50 V,+/- 10%, X7R, 1210; Manufacturer: TDK; Polarized: N; CompType: Capacitor; Value: 4.7uF; U/M: EA; Cap_F: 0.0000047; Tolerance_%: 10; ESR_ohm: 0.003166; Value1: 0.003166 ohm; VDC_V: 50; Value2: 50V; IRMS_A: 4.13311; TaMin_C: -55; TaMax_C: 125; Cap_Case: 1210; SizeArea_mm2: 8; SizeAreaWB_mm2: 14.7; SizeX_mm: 3.2; SizeY_mm: 2.5; SizeZ_mm: 2.8; AEC Category: Q200
signal-integrity model Cap
simulation model Cap
footprint 1210_280
pins: 1, 2

## C3225X7R2A105K200AA
designator C?  ValueDisplayed: 1µF  (hidden comment: C3225X7R2A105K200AA)
CAP, CERM, 1 µF, 100 V,+/- 10%, X7R, 1210; Manufacturer: TDK; Polarized: N; CompType: Capacitor; Value: 1uF; U/M: EA; Cap_F: 0.000001; Tolerance_%: 10; ESR_ohm: 0.004956; Value1: 0.004956 ohm; VDC_V: 100; Value2: 100V; IRMS_A: 3.30731; TaMin_C: -55; TaMax_C: 125; Cap_Case: 1210; SizeArea_mm2: 8; SizeAreaWB_mm2: 14.7; SizeX_mm: 3.2; SizeY_mm: 2.5; SizeZ_mm: 2.2; AEC Category: Q200; Green_Lifecycle: Active; Green_REACh: Passed
signal-integrity model Cap
simulation model Cap
footprint 1210_220
footprint 1210_220M
footprint 1210_220L
pins: 1, 2

## C3225X7R2A155K200AB
designator C?  ValueDisplayed: 1.5µF  (hidden comment: C3225X7R2A155K200AB)
CAP, CERM, 1.5 µF, 100 V,+/- 10%, X7R, 1210; Manufacturer: TDK; Polarized: N; CompType: Capacitor; Value: 1.5uF; U/M: EA; Cap_F: 0.0000015; Tolerance_%: 10; ESR_ohm: 0.003867; Value1: 0.003867 ohm; VDC_V: 100; Value2: 100V; IRMS_A: 3.74252; TaMin_C: -55; TaMax_C: 125; Cap_Case: 1210; SizeArea_mm2: 8; SizeAreaWB_mm2: 14.7; SizeX_mm: 3.2; SizeY_mm: 2.5; SizeZ_mm: 2.2; AEC Category: Q200
signal-integrity model Cap
simulation model Cap
footprint 1210_220
footprint 1210_220M
footprint 1210_220L
pins: 1, 2

## C3225X7R2A334K200AA
designator C?  ValueDisplayed: 0.33µF  (hidden comment: C3225X7R2A334K200AA)
CAP, CERM, 0.33 µF, 100 V,+/- 10%, X7R, 1210; Manufacturer: TDK; Polarized: N; CompType: Capacitor; Value: 0.33uF; U/M: EA; Cap_F: 0.00000033; Tolerance_%: 10; ESR_ohm: 0.010566; Value1: 0.010566 ohm; VDC_V: 100; Value2: 100V; IRMS_A: 2.2725; TaMin_C: -55; TaMax_C: 125; Cap_Case: 1210; SizeArea_mm2: 8; SizeAreaWB_mm2: 14.7; SizeX_mm: 3.2; SizeY_mm: 2.5; SizeZ_mm: 2.2; AEC Category: Q200
signal-integrity model Cap
simulation model Cap
footprint 1210_220
footprint 1210_220M
footprint 1210_220L
pins: 1, 2

## C3225X7R2A474K200AA
designator C?  ValueDisplayed: 0.47µF  (hidden comment: C3225X7R2A474K200AA)
CAP, CERM, 0.47 µF, 100 V,+/- 10%, X7R, 1210; Manufacturer: TDK; Polarized: N; CompType: Capacitor; Value: 0.47uF; U/M: EA; Cap_F: 0.00000047; Tolerance_%: 10; ESR_ohm: 0.009164; Value1: 0.009164 ohm; VDC_V: 100; Value2: 100V; IRMS_A: 2.43674; TaMin_C: -55; TaMax_C: 125; Cap_Case: 1210; SizeArea_mm2: 8; SizeAreaWB_mm2: 14.7; SizeX_mm: 3.2; SizeY_mm: 2.5; SizeZ_mm: 2.2; AEC Category: Q200
signal-integrity model Cap
simulation model Cap
footprint 1210_220
footprint 1210_220M
footprint 1210_220L
pins: 1, 2

## C3225X7R2A684K160AA
designator C?  ValueDisplayed: 0.68µF  (hidden comment: C3225X7R2A684K160AA)
CAP, CERM, 0.68 µF, 100 V,+/- 10%, X7R, 1210; Manufacturer: TDK; Polarized: N; CompType: Capacitor; Value: 0.68uF; U/M: EA; Cap_F: 0.00000068; Tolerance_%: 10; ESR_ohm: 0.005781; Value1: 0.005781 ohm; VDC_V: 100; Value2: 100V; IRMS_A: 3.06493; TaMin_C: -55; TaMax_C: 125; Cap_Case: 1210; SizeArea_mm2: 8; SizeAreaWB_mm2: 14.7; SizeX_mm: 3.2; SizeY_mm: 2.5; SizeZ_mm: 1.8; AEC Category: Q200
signal-integrity model Cap
simulation model Cap
footprint 1210_180
footprint 1210_180M
footprint 1210_180L
pins: 1, 2

## C3225X7S0J476M250AC
designator C?  ValueDisplayed: 47µF  (hidden comment: C3225X7S0J476M250AC)
CAP, CERM, 47 µF, 6.3 V,+/- 20%, X7S, 1210; Manufacturer: TDK; Polarized: N; CompType: Capacitor; Value: 47uF; U/M: EA; Cap_F: 0.000047; Tolerance_%: 20; ESR_ohm: 0.003602; Value1: 0.003602 ohm; VDC_V: 6.3; Value2: 6.3V; IRMS_A: 3.87414; TaMin_C: -55; TaMax_C: 125; Cap_Case: 1210; SizeArea_mm2: 8; SizeAreaWB_mm2: 14.7; SizeX_mm: 3.2; SizeY_mm: 2.5; SizeZ_mm: 2.8; AEC Category: Q200
signal-integrity model Cap
simulation model Cap
footprint 1210_280
pins: 1, 2

## C3225X7S1H106K250AB
designator C?  ValueDisplayed: 10µF  (hidden comment: C3225X7S1H106K250AB)
CAP, CERM, 10 µF, 50 V,+/- 10%, X7S, 1210; Manufacturer: TDK; Polarized: N; CompType: Capacitor; Value: 10uF; U/M: EA; Cap_F: 0.00001; Tolerance_%: 10; ESR_ohm: 0.002827; Value1: 0.002827 ohm; VDC_V: 50; Value2: 50V; IRMS_A: 4.37286; TaMin_C: -55; TaMax_C: 125; Cap_Case: 1210; SizeArea_mm2: 8; SizeAreaWB_mm2: 14.7; SizeX_mm: 3.2; SizeY_mm: 2.5; SizeZ_mm: 2.8; AEC Category: Q200; Green_Lifecycle: Active; Green_REACh: Passed
signal-integrity model Cap
simulation model Cap
footprint 1210_280
pins: 1, 2

## C3225X7S1H685K250AB
designator C?  ValueDisplayed: 6.8µF  (hidden comment: C3225X7S1H685K250AB)
CAP, CERM, 6.8 µF, 50 V,+/- 10%, X7S, 1210; Manufacturer: TDK; Polarized: N; CompType: Capacitor; Value: 6.8uF; U/M: EA; Cap_F: 0.0000068; Tolerance_%: 10; ESR_ohm: 0.002885; Value1: 0.002885 ohm; VDC_V: 50; Value2: 50V; IRMS_A: 4.32962; TaMin_C: -55; TaMax_C: 125; Cap_Case: 1210; SizeArea_mm2: 8; SizeAreaWB_mm2: 14.7; SizeX_mm: 3.2; SizeY_mm: 2.5; SizeZ_mm: 2.8; AEC Category: Q200
signal-integrity model Cap
simulation model Cap
footprint 1210_280
pins: 1, 2

## C3225X7S2A335M200AB
designator C?  ValueDisplayed: 3.3µF  (hidden comment: C3225X7S2A335M200AB)
CAP, CERM, 3.3 µF, 100 V,+/- 20%, X7S, 1210; Manufacturer: TDK; Polarized: N; CompType: Capacitor; Value: 3.3uF; U/M: EA; Cap_F: 0.0000033; Tolerance_%: 20; VDC_V: 100; Value2: 100V; TaMin_C: -55; TaMax_C: 125; Cap_Case: 1210; SizeArea_mm2: 8; SizeAreaWB_mm2: 14.7; SizeX_mm: 3.2; SizeY_mm: 2.5; SizeZ_mm: 1.35; AEC Category: Q200; Green_Lifecycle: NRND; Green_REACh: Passed
signal-integrity model Cap
simulation model Cap
footprint 1210
footprint 1210M
footprint 1210L
pins: 1, 2

## C3225X7S2A475K200AB
designator C?  ValueDisplayed: 4.7µF  (hidden comment: C3225X7S2A475K200AB)
CAP, CERM, 4.7 µF, 100 V,+/- 10%, X7S, 1210; Manufacturer: TDK; Polarized: N; CompType: Capacitor; Value: 4.7uF; U/M: EA; Cap_F: 0.0000047; Tolerance_%: 10; ESR_ohm: 0.004236; Value1: 0.004236 ohm; VDC_V: 100; Value2: 100V; IRMS_A: 3.57337; TaMin_C: -55; TaMax_C: 125; Cap_Case: 1210; SizeArea_mm2: 8; SizeAreaWB_mm2: 14.7; SizeX_mm: 3.2; SizeY_mm: 2.5; SizeZ_mm: 2.2; AEC Category: Q200; Green_Lifecycle: Active; Green_REACh: Passed
signal-integrity model Cap
simulation model Cap
footprint 1210_220
footprint 1210_220M
footprint 1210_220L
pins: 1, 2

## C3225X7S2A475K200AE
designator C?  ValueDisplayed: 4.7µF  (hidden comment: C3225X7S2A475K200AE)
CAP, CERM, 4.7 µF, 100 V,+/- 10%, X7S, 1210; Manufacturer: TDK; Polarized: N; CompType: Capacitor; Value: 4.7uF; U/M: EA; Cap_F: 0.0000047; Tolerance_%: 10; VDC_V: 100; Value2: 100V; TaMin_C: -55; TaMax_C: 125; Cap_Case: 1210; SizeArea_mm2: 8; SizeAreaWB_mm2: 14.7; SizeX_mm: 3.2; SizeY_mm: 2.5; SizeZ_mm: 1.35; AEC Category: Q200; Green_Lifecycle: Active; Green_REACh: Passed
signal-integrity model Cap
simulation model Cap
footprint 1210
footprint 1210M
footprint 1210L
pins: 1, 2

## C3225X7T2J104K160AC
designator C?  ValueDisplayed: 0.1µF  (hidden comment: C3225X7T2J104K160AC)
CAP, CERM, 0.1 µF, 630 V,+/- 10%, X7T, 1210; Manufacturer: TDK; Polarized: N; CompType: Capacitor; Value: 0.1uF; U/M: EA; Cap_F: 0.0000001; Tolerance_%: 10; VDC_V: 630; Value2: 630V; TaMin_C: -55; TaMax_C: 125; Cap_Case: 1210; SizeArea_mm2: 8; SizeAreaWB_mm2: 14.7; SizeX_mm: 3.2; SizeY_mm: 2.5; SizeZ_mm: 1.35; AEC Category: Q200; Green_Lifecycle: Not Set; Green_REACh: Incomplete
signal-integrity model Cap
simulation model Cap
footprint 1210
footprint 1210M
footprint 1210L
pins: 1, 2

## C3225X7T2J104K160AE
designator C?  ValueDisplayed: 0.1µF  (hidden comment: C3225X7T2J104K160AE)
CAP, CERM, 0.1 µF, 630 V,+/- 10%, X7T, 1210; Manufacturer: TDK; Polarized: N; CompType: Capacitor; Value: 0.1uF; U/M: EA; Cap_F: 0.0000001; Tolerance_%: 10; VDC_V: 630; Value2: 630V; TaMin_C: -55; TaMax_C: 125; Cap_Case: 1210; SizeArea_mm2: 8; SizeAreaWB_mm2: 14.7; SizeX_mm: 3.2; SizeY_mm: 2.5; SizeZ_mm: 1.8; AEC Category: Q200; Green_Lifecycle: Not Set; Green_REACh: Incomplete
signal-integrity model Cap
simulation model Cap
footprint 1210_180
footprint 1210_180M
footprint 1210_180L
pins: 1, 2

## C3225X7T2J104M160AC
designator C?  ValueDisplayed: 0.1µF  (hidden comment: C3225X7T2J104M160AC)
CAP, CERM, 0.1 µF, 630 V,+/- 20%, X7T, 1210; Manufacturer: TDK; Polarized: N; CompType: Capacitor; Value: 0.1uF; U/M: EA; Cap_F: 0.0000001; Tolerance_%: 20; VDC_V: 630; Value2: 630V; TaMin_C: -55; TaMax_C: 125; Cap_Case: 1210; SizeArea_mm2: 8; SizeAreaWB_mm2: 14.7; SizeX_mm: 3.2; SizeY_mm: 2.5; SizeZ_mm: 1.8; AEC Category: Q200; Green_Lifecycle: Not Set; Green_REACh: Incomplete
signal-integrity model Cap
simulation model Cap
footprint 1210_180
footprint 1210_180M
footprint 1210_180L
pins: 1, 2

## C3225X7T2J104M160AE
designator C?  ValueDisplayed: 0.1µF  (hidden comment: C3225X7T2J104M160AE)
CAP, CERM, 0.1 µF, 630 V,+/- 20%, X7T, 1210; Manufacturer: TDK; Polarized: N; CompType: Capacitor; Value: 0.1uF; U/M: EA; Cap_F: 0.0000001; Tolerance_%: 20; VDC_V: 630; Value2: 630V; TaMin_C: -55; TaMax_C: 125; Cap_Case: 1210; SizeArea_mm2: 8; SizeAreaWB_mm2: 14.7; SizeX_mm: 3.2; SizeY_mm: 2.5; SizeZ_mm: 1.8; AEC Category: Q200; Green_Lifecycle: Not Set; Green_REACh: Incomplete
signal-integrity model Cap
simulation model Cap
footprint 1210_180
footprint 1210_180M
footprint 1210_180L
pins: 1, 2

## C4532C0G2A473J200KA
designator C?  ValueDisplayed: 0.047µF  (hidden comment: C4532C0G2A473J200KA)
CAP, CERM, 0.047 µF, 100 V,+/- 5%, C0G/NP0, 1812; Manufacturer: TDK; Polarized: N; CompType: Capacitor; Value: 0.047uF; U/M: EA; Cap_F: 0.000000047; Tolerance_%: 5; VDC_V: 100; Value2: 100V; TaMin_C: -55; TaMax_C: 125; Cap_Case: 1812; SizeArea_mm2: 14.4; SizeAreaWB_mm2: 23.1; SizeX_mm: 4.5; SizeY_mm: 3.2; SizeZ_mm: 1.35; AEC Category: Q200; Green_Lifecycle: Active; Green_REACh: Passed
signal-integrity model Cap
simulation model Cap
footprint 1812
footprint 1812M
footprint 1812L
footprint 1812_HV
pins: 1, 2

## C4532X5R0J686M280KA
designator C?  ValueDisplayed: 68µF  (hidden comment: C4532X5R0J686M280KA)
CAP, CERM, 68 µF, 6.3 V,+/- 20%, X5R, 1812; Manufacturer: TDK; Polarized: N; CompType: Capacitor; Value: 68uF; U/M: EA; Cap_F: 0.000068; Tolerance_%: 20; ESR_ohm: 0.005027; Value1: 0.005027 ohm; VDC_V: 6.3; Value2: 6.3V; IRMS_A: 3.42123; TaMin_C: -55; TaMax_C: 85; Cap_Case: 1812; SizeArea_mm2: 14.4; SizeAreaWB_mm2: 23.1; SizeX_mm: 4.5; SizeY_mm: 3.2; AEC Category: Q200; Green_Lifecycle: NRND; Green_REACh: Passed
signal-integrity model Cap
simulation model Cap
footprint 1812_320
footprint 1812_320M
footprint 1812_320L
pins: 1, 2

## C4532X5R1A107M280KC
designator C?  ValueDisplayed: 100µF  (hidden comment: C4532X5R1A107M280KC)
CAP, CERM, 100 µF, 10 V,+/- 20%, X5R, 1812; Manufacturer: TDK; Polarized: N; CompType: Capacitor; Value: 100uF; U/M: EA; Cap_F: 0.0001; Tolerance_%: 20; ESR_ohm: 0.005426; Value1: 0.005426 ohm; VDC_V: 10; Value2: 10V; IRMS_A: 3.29279; TaMin_C: -55; TaMax_C: 85; Cap_Case: 1812; SizeArea_mm2: 14.4; SizeAreaWB_mm2: 23.1; SizeX_mm: 4.5; SizeY_mm: 3.2; AEC Category: Q200
signal-integrity model Cap
simulation model Cap
footprint 1812_320
footprint 1812_320M
footprint 1812_320L
pins: 1, 2

## C4532X5R1A476M280KA
designator C?  ValueDisplayed: 47µF  (hidden comment: C4532X5R1A476M280KA)
CAP, CERM, 47 µF, 10 V,+/- 20%, X5R, 1812; Manufacturer: TDK; Polarized: N; CompType: Capacitor; Value: 47uF; U/M: EA; Cap_F: 0.000047; Tolerance_%: 20; ESR_ohm: 0.00453; Value1: 0.00453 ohm; VDC_V: 10; Value2: 10V; IRMS_A: 3.60384; TaMin_C: -55; TaMax_C: 85; Cap_Case: 1812; SizeArea_mm2: 14.4; SizeAreaWB_mm2: 23.1; SizeX_mm: 4.5; SizeY_mm: 3.2; AEC Category: Q200; Green_Lifecycle: Active; Green_REACh: Passed
signal-integrity model Cap
simulation model Cap
footprint 1812_320
footprint 1812_320M
footprint 1812_320L
pins: 1, 2

## C4532X5R1C336M250KA
designator C?  ValueDisplayed: 33µF  (hidden comment: C4532X5R1C336M250KA)
CAP, CERM, 33 µF, 16 V,+/- 20%, X5R, 1812; Manufacturer: TDK; Polarized: N; CompType: Capacitor; Value: 33uF; U/M: EA; Cap_F: 0.000033; Tolerance_%: 20; ESR_ohm: 0.002427; Value1: 0.002427 ohm; VDC_V: 16; Value2: 16V; IRMS_A: 4.92344; TaMin_C: -55; TaMax_C: 85; Cap_Case: 1812; SizeArea_mm2: 14.4; SizeAreaWB_mm2: 23.1; SizeX_mm: 4.5; SizeY_mm: 3.2; SizeZ_mm: 2.8; AEC Category: Q200
signal-integrity model Cap
simulation model Cap
footprint 1812_280
footprint 1812_280M
footprint 1812_280L
pins: 1, 2

## C4532X5R1E156M250KA
designator C?  ValueDisplayed: 15µF  (hidden comment: C4532X5R1E156M250KA)
CAP, CERM, 15 µF, 25 V,+/- 20%, X5R, 1812; Manufacturer: TDK; Polarized: N; CompType: Capacitor; Value: 15uF; U/M: EA; Cap_F: 0.000015; Tolerance_%: 20; ESR_ohm: 0.002115; Value1: 0.002115 ohm; VDC_V: 25; Value2: 25V; IRMS_A: 5.2737; TaMin_C: -55; TaMax_C: 85; Cap_Case: 1812; SizeArea_mm2: 14.4; SizeAreaWB_mm2: 23.1; SizeX_mm: 4.5; SizeY_mm: 3.2; SizeZ_mm: 2.8; AEC Category: Q200
signal-integrity model Cap
simulation model Cap
footprint 1812_280
footprint 1812_280M
footprint 1812_280L
pins: 1, 2

## C4532X5R1E156M280KA
designator C?  ValueDisplayed: 15µF  (hidden comment: C4532X5R1E156M280KA)
CAP, CERM, 15 µF, 25 V,+/- 20%, X5R, 1812; Manufacturer: TDK; Polarized: N; CompType: Capacitor; Value: 15uF; U/M: EA; Cap_F: 0.000015; Tolerance_%: 20; ESR_ohm: 0.002488; Value1: 0.002488 ohm; VDC_V: 25; Value2: 25V; IRMS_A: 4.86254; TaMin_C: -55; TaMax_C: 85; Cap_Case: 1812; SizeArea_mm2: 14.4; SizeAreaWB_mm2: 23.1; SizeX_mm: 4.5; SizeY_mm: 3.2; AEC Category: Q200
signal-integrity model Cap
simulation model Cap
footprint 1812_320
footprint 1812_320M
footprint 1812_320L
pins: 1, 2

## C4532X5R1E226M250KA
designator C?  ValueDisplayed: 22µF  (hidden comment: C4532X5R1E226M250KA)
CAP, CERM, 22 µF, 25 V,+/- 20%, X5R, 1812; Manufacturer: TDK; Polarized: N; CompType: Capacitor; Value: 22uF; U/M: EA; Cap_F: 0.000022; Tolerance_%: 20; ESR_ohm: 0.002434; Value1: 0.002434 ohm; VDC_V: 25; Value2: 25V; IRMS_A: 4.91649; TaMin_C: -55; TaMax_C: 85; Cap_Case: 1812; SizeArea_mm2: 14.4; SizeAreaWB_mm2: 23.1; SizeX_mm: 4.5; SizeY_mm: 3.2; SizeZ_mm: 2.8; AEC Category: Q200
signal-integrity model Cap
simulation model Cap
footprint 1812_280
footprint 1812_280M
footprint 1812_280L
pins: 1, 2

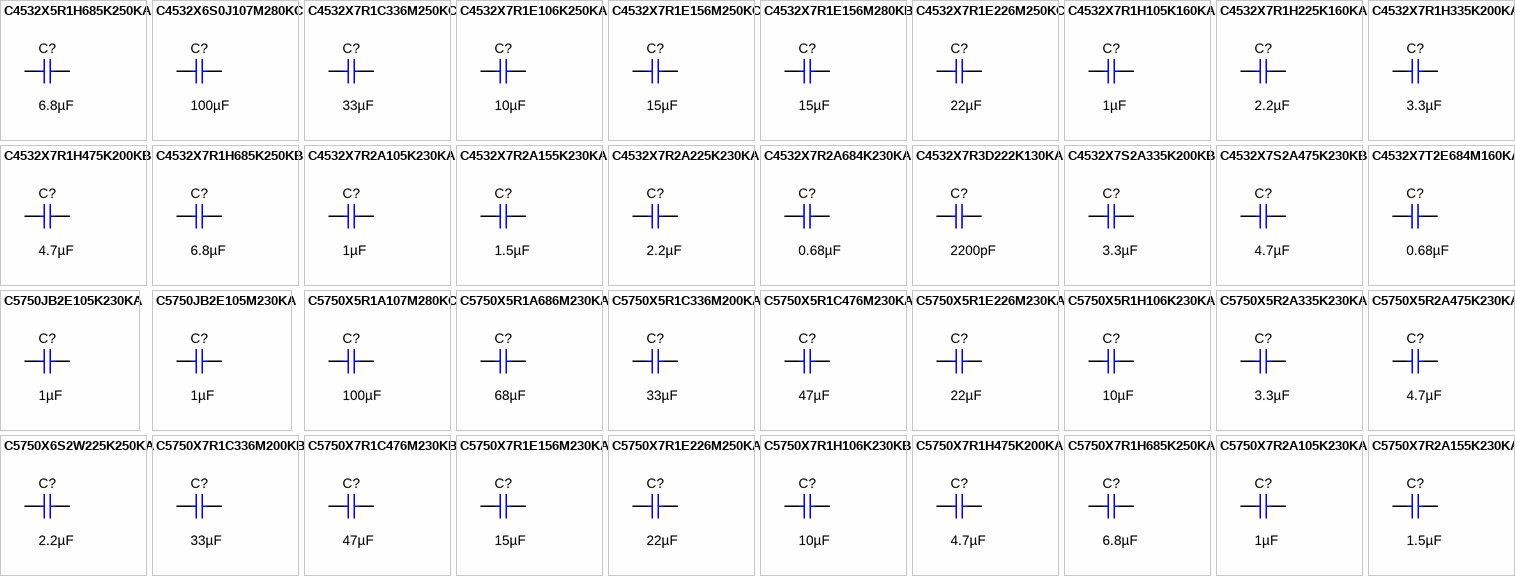
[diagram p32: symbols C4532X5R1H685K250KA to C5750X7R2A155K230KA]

## C4532X5R1H685K250KA
designator C?  ValueDisplayed: 6.8µF  (hidden comment: C4532X5R1H685K250KA)
CAP, CERM, 6.8 µF, 50 V,+/- 10%, X5R, 1812; Manufacturer: TDK; Polarized: N; CompType: Capacitor; Value: 6.8uF; U/M: EA; Cap_F: 0.0000068; Tolerance_%: 10; ESR_ohm: 0.002621; Value1: 0.002621 ohm; VDC_V: 50; Value2: 50V; IRMS_A: 4.73771; TaMin_C: -55; TaMax_C: 85; Cap_Case: 1812; SizeArea_mm2: 14.4; SizeAreaWB_mm2: 23.1; SizeX_mm: 4.5; SizeY_mm: 3.2; SizeZ_mm: 2.8; AEC Category: Q200; Green_Lifecycle: NRND; Green_REACh: Passed
signal-integrity model Cap
simulation model Cap
footprint 1812_280
footprint 1812_280M
footprint 1812_280L
pins: 1, 2

## C4532X6S0J107M280KC
designator C?  ValueDisplayed: 100µF  (hidden comment: C4532X6S0J107M280KC)
CAP, CERM, 100 µF, 6.3 V,+/- 20%, X6S, 1812; Manufacturer: TDK; Polarized: N; CompType: Capacitor; Value: 100uF; U/M: EA; Cap_F: 0.0001; Tolerance_%: 20; ESR_ohm: 0.005426; Value1: 0.005426 ohm; VDC_V: 6.3; Value2: 6.3V; IRMS_A: 3.29279; TaMin_C: -55; TaMax_C: 105; Cap_Case: 1812; SizeArea_mm2: 14.4; SizeAreaWB_mm2: 23.1; SizeX_mm: 4.5; SizeY_mm: 3.2; AEC Category: Q200; Green_Lifecycle: Active; Green_REACh: Passed
signal-integrity model Cap
simulation model Cap
footprint 1812_320
footprint 1812_320M
footprint 1812_320L
pins: 1, 2

## C4532X7R1C336M250KC
designator C?  ValueDisplayed: 33µF  (hidden comment: C4532X7R1C336M250KC)
CAP, CERM, 33 µF, 16 V,+/- 20%, X7R, 1812; Manufacturer: TDK; Polarized: N; CompType: Capacitor; Value: 33uF; U/M: EA; Cap_F: 0.000033; Tolerance_%: 20; ESR_ohm: 0.002427; Value1: 0.002427 ohm; VDC_V: 16; Value2: 16V; IRMS_A: 4.92344; TaMin_C: -55; TaMax_C: 125; Cap_Case: 1812; SizeArea_mm2: 14.4; SizeAreaWB_mm2: 23.1; SizeX_mm: 4.5; SizeY_mm: 3.2; SizeZ_mm: 2.8; AEC Category: Q200
signal-integrity model Cap
simulation model Cap
footprint 1812_280
footprint 1812_280M
footprint 1812_280L
pins: 1, 2

## C4532X7R1E106K250KA
designator C?  ValueDisplayed: 10µF  (hidden comment: C4532X7R1E106K250KA)
CAP, CERM, 10 µF, 25 V,+/- 10%, X7R, 1812; Manufacturer: TDK; Polarized: N; CompType: Capacitor; Value: 10uF; U/M: EA; Cap_F: 0.00001; Tolerance_%: 10; ESR_ohm: 0.00174; Value1: 0.00174 ohm; VDC_V: 25; Value2: 25V; IRMS_A: 5.81481; TaMin_C: -55; TaMax_C: 125; Cap_Case: 1812; SizeArea_mm2: 14.4; SizeAreaWB_mm2: 23.1; SizeX_mm: 4.5; SizeY_mm: 3.2; SizeZ_mm: 2.8; AEC Category: Q200; Green_Lifecycle: Active; Green_REACh: Passed
signal-integrity model Cap
simulation model Cap
footprint 1812_280
footprint 1812_280M
footprint 1812_280L
pins: 1, 2

## C4532X7R1E156M250KC
designator C?  ValueDisplayed: 15µF  (hidden comment: C4532X7R1E156M250KC)
CAP, CERM, 15 µF, 25 V,+/- 20%, X7R, 1812; Manufacturer: TDK; Polarized: N; CompType: Capacitor; Value: 15uF; U/M: EA; Cap_F: 0.000015; Tolerance_%: 20; ESR_ohm: 0.002115; Value1: 0.002115 ohm; VDC_V: 25; Value2: 25V; IRMS_A: 5.2737; TaMin_C: -55; TaMax_C: 125; Cap_Case: 1812; SizeArea_mm2: 14.4; SizeAreaWB_mm2: 23.1; SizeX_mm: 4.5; SizeY_mm: 3.2; SizeZ_mm: 2.8; AEC Category: Q200
signal-integrity model Cap
simulation model Cap
footprint 1812_280
footprint 1812_280M
footprint 1812_280L
pins: 1, 2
